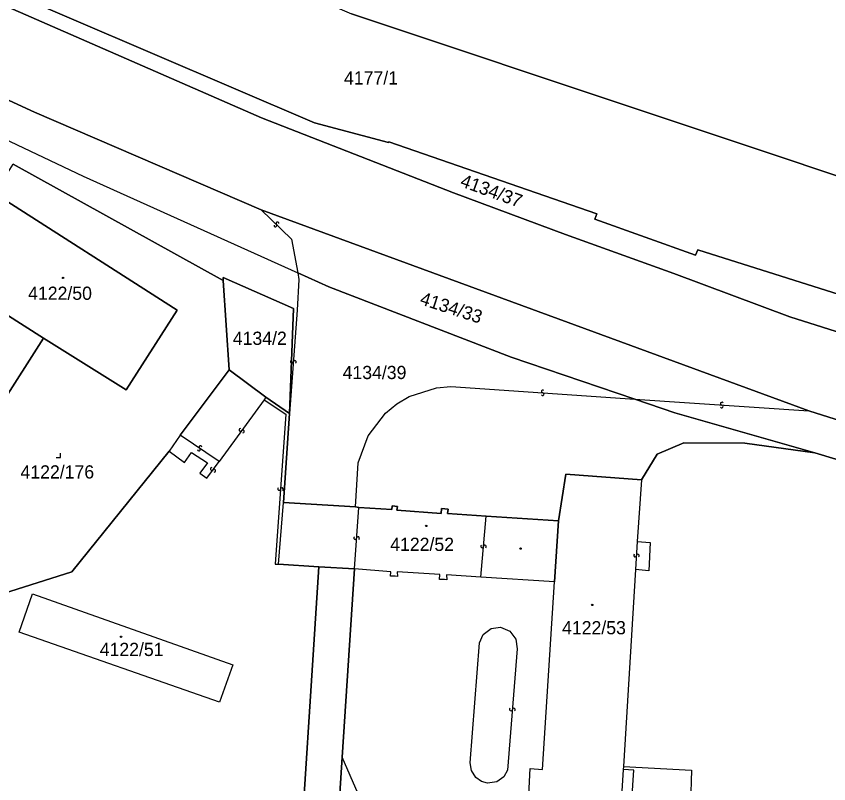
# Model space of a CAD drawing. Extents: x -598233 to -596890, y -1157848 to -1156431.
# Drawn here: x -597945.2 to -597840.5, y -1157611.2 to -1157512.4 of the extents above; entities that cross this region are included whole.
import ezdxf

# ---------------------------------------------------------------- set-up
doc = ezdxf.new("R2010")
doc.units = 0
for name, color, linetype in [('Level 1', 7, 'Continuous'), ('Level 13', 7, 'Continuous'), ('Level 3', 7, 'Continuous'), ('Level 4', 7, 'Continuous'), ('Level 5', 7, 'Continuous'), ('Level 57', 7, 'Continuous'), ('Level 60', 7, 'Continuous'), ('Vrstva 60', 7, 'Continuous')]:
    doc.layers.add(name, color=color, linetype=linetype)

msp = doc.modelspace()

# ---------------------------------------------------------------- linework, layer by layer
at = {"layer": 'Level 1'}
for points in [[(-597913.6, -1157537.3), (-597942.81, -1157524.72), (-597959.99, -1157516.81), (-597976.93, -1157508.35), (-597986.84, -1157503.35), (-597996.75, -1157497.54), (-598004.99, -1157491.79), (-598011.47, -1157486.71), (-598075.95, -1157430.81), (-598078.56, -1157429.36)], [(-598038.09, -1157453.32), (-598021.72, -1157467.23), (-598015.08, -1157472.26), (-598001.59, -1157481.46), (-597987.42, -1157490.71), (-597984.33, -1157492.5), (-597975.77, -1157497.25), (-597953.48, -1157507.99), (-597913.56, -1157525.44), (-597888.84, -1157535.12), (-597874.43, -1157540.49), (-597860.48, -1157545.51), (-597845.54, -1157551.08), (-597825.32, -1157557.5)], [(-597823.15, -1157553.3), (-597823.53, -1157553.16), (-597857.39, -1157542.48), (-597857.69, -1157543.15), (-597870.63, -1157538.52), (-597870.37, -1157537.84), (-597897.17, -1157528.53), (-597897.21, -1157528.65), (-597906.72, -1157526.08), (-597948.51, -1157508.17), (-597952.1, -1157506.41), (-597975.49, -1157494.97), (-597983.53, -1157490.82)], [(-597901.96, -1157512.06), (-597824.41, -1157537.97)], [(-597979.31, -1157512.67), (-597936.54, -1157532.96), (-597908.9, -1157545.41)], [(-597945.53, -1157531.41), (-597918.5, -1157546.39)], [(-597947.94, -1157535.19), (-597924.43, -1157550.22), (-597931, -1157560.5), (-597941.63, -1157553.83)], [(-597913.6, -1157537.3), (-597843.08, -1157563.22)], [(-597989.58, -1157543.55), (-597978.7, -1157561.72), (-597968.17, -1157576.4), (-597956.12, -1157589.86), (-597953.04, -1157588.7), (-597937.98, -1157583.96), (-597925.46, -1157568.41)], [(-597954.59, -1157545.6), (-597967.26, -1157565.3), (-597970.4, -1157563.29), (-597972.89, -1157567.17), (-597969.79, -1157569.25), (-597971.11, -1157571.47), (-597958.18, -1157579.74), (-597941.63, -1157553.83)], [(-597954.59, -1157545.6), (-597941.63, -1157553.83)], [(-597865.5, -1157561.69), (-597881.42, -1157556.29), (-597904.9, -1157547.21), (-597908.9, -1157545.41)], [(-597909.97, -1157563.55), (-597909.45, -1157550.01), (-597918.51, -1157546.01), (-597918.5, -1157546.39)], [(-597918.5, -1157546.39), (-597917.73, -1157557.9)], [(-597924.02, -1157566.34), (-597917.73, -1157557.9)], [(-597917.73, -1157557.9), (-597912.99, -1157561.42)], [(-597912.99, -1157561.42), (-597909.97, -1157563.55)], [(-597842.3, -1157568.62), (-597860.35, -1157563.44), (-597865.5, -1157561.69)], [(-597457.99, -1157648.3), (-597510.31, -1157637.9), (-597566.92, -1157626.51), (-597621.93, -1157615.29), (-597674.27, -1157604.65), (-597727.52, -1157593.95), (-597766.74, -1157585.27), (-597793.63, -1157578.19), (-597810.63, -1157573.46), (-597843.08, -1157563.22)], [(-597909.97, -1157563.55), (-597910.72, -1157575.03)], [(-597924.02, -1157566.34), (-597925.46, -1157568.41)], [(-597864.63, -1157572.11), (-597862.63, -1157568.77), (-597859.17, -1157567.31), (-597851.33, -1157567.38), (-597842.3, -1157568.62)], [(-597842.3, -1157568.62), (-597811.99, -1157577.74), (-597794.73, -1157582.38), (-597777.42, -1157587.05)], [(-597875.32, -1157577.36), (-597874.38, -1157571.36), (-597864.63, -1157572.11)], [(-597864.63, -1157572.11), (-597865.17, -1157580.04)], [(-597911.36, -1157582.95), (-597910.72, -1157575.03)], [(-597910.72, -1157575.03), (-597901.48, -1157575.59)], [(-597901.48, -1157575.59), (-597901.04, -1157575.64)], [(-597901.04, -1157575.64), (-597896.77, -1157575.93), (-597896.74, -1157575.45), (-597896.05, -1157575.53), (-597896.15, -1157576), (-597890.42, -1157576.43), (-597890.39, -1157575.78), (-597889.53, -1157575.88), (-597889.61, -1157576.42), (-597884.62, -1157576.75)], [(-597884.62, -1157576.75), (-597875.32, -1157577.36)], [(-597875.83, -1157585.25), (-597875.32, -1157577.36)], [(-597865.17, -1157580.04), (-597863.5, -1157580.15), (-597863.7, -1157583.8), (-597865.39, -1157583.63)], [(-597906.18, -1157583.28), (-597909.06, -1157627.95), (-598044.6, -1157619.18), (-598047.12, -1157656.06), (-598034.89, -1157656.85)], [(-597911.36, -1157582.95), (-597906.18, -1157583.28)], [(-597906.18, -1157583.28), (-597901.61, -1157583.57)], [(-597903.17, -1157607.81), (-597901.61, -1157583.57)], [(-597885.31, -1157584.61), (-597889.73, -1157584.35), (-597889.7, -1157584.98), (-597889.98, -1157584.95), (-597890.35, -1157584.93), (-597890.66, -1157584.95), (-597890.58, -1157584.3), (-597896.1, -1157583.95), (-597896.06, -1157584.55), (-597896.34, -1157584.52), (-597896.66, -1157584.51), (-597896.97, -1157584.52), (-597896.9, -1157583.93), (-597901.61, -1157583.57)], [(-597865.39, -1157583.63), (-597866.95, -1157609.01)], [(-597875.83, -1157585.25), (-597885.31, -1157584.61)], [(-597867, -1157609.41), (-597867.48, -1157617.05), (-597877.85, -1157616.75), (-597877.6, -1157612.76), (-597879.16, -1157612.66), (-597878.98, -1157609.3), (-597877.38, -1157609.4), (-597875.83, -1157585.25)], [(-597917.27, -1157595.91), (-597918.96, -1157600.75), (-597944.77, -1157591.72), (-597943.04, -1157586.79), (-597917.27, -1157595.91)], [(-597964.2, -1157694.04), (-597963.85, -1157688.75), (-597961.55, -1157671.94), (-597959.51, -1157642.87), (-597958.41, -1157630.64), (-597940.04, -1157631.73), (-597904.85, -1157633.91), (-597903.17, -1157607.81)], [(-597858.3, -1157613.77), (-597865.87, -1157613.39), (-597865.62, -1157609.5), (-597867, -1157609.41)], [(-597866.95, -1157609.01), (-597858.19, -1157609.5), (-597858.3, -1157613.77)]]:
    msp.add_lwpolyline(points, dxfattribs=at)
at = {"layer": 'Level 13'}
for centre, start, end in [((-597911.77, -1157539.31), 173.2026, 45.7926), ((-597911.51, -1157539.05), 353.4171, 225.5151), ((-597909.65, -1157556.87), 122.8681, 355.4581), ((-597909.29, -1157556.9), 303.0825, 175.1805), ((-597877.34, -1157560.7), 33.4865, 265.5845), ((-597877.36, -1157561.06), 213.272, 85.862), ((-597854.28, -1157562.28), 33.4688, 265.5668), ((-597854.3, -1157562.64), 213.2543, 85.8443), ((-597916.28, -1157565.64), 91.0453, 323.6353), ((-597915.98, -1157565.86), 271.2597, 143.3577), ((-597921.62, -1157568.18), 183.2608, 55.3588), ((-597921.42, -1157567.88), 3.0463, 235.6363), ((-597919.96, -1157570.69), 91.5351, 323.6331), ((-597919.66, -1157570.91), 271.3206, 143.9106), ((-597911.3, -1157573.28), 123.041, 355.631), ((-597910.94, -1157573.3), 303.2555, 175.3535), ((-597901.5, -1157579.59), 123.2614, 355.3594), ((-597901.14, -1157579.61), 303.047, 175.637), ((-597885.15, -1157580.66), 122.3558, 354.4538), ((-597884.79, -1157580.7), 302.1414, 174.7314), ((-597865.46, -1157581.83), 123.6515, 356.2415), ((-597865.1, -1157581.85), 303.866, 175.964), ((-597881.44, -1157601.67), 122.7372, 355.3272), ((-597881.08, -1157601.7), 302.9516, 175.0496)]:
    msp.add_arc(centre, 0.184, start, end, dxfattribs=at)
at = {"layer": 'Level 3'}
for points in [[(-597913.6, -1157537.3), (-597909.69, -1157541.07), (-597908.9, -1157545.41)], [(-597908.9, -1157545.41), (-597908.74, -1157546.3), (-597908.97, -1157550.22), (-597909.97, -1157563.55)], [(-597901.48, -1157575.59), (-597901.1, -1157569.9), (-597899.83, -1157566.43), (-597897.58, -1157563.5), (-597896.12, -1157562.3), (-597894.56, -1157561.37), (-597891.04, -1157560.24), (-597889.2, -1157560.08), (-597865.5, -1157561.69)], [(-597913.23, -1157561.77), (-597919.03, -1157569.72)], [(-597912.99, -1157561.42), (-597913.23, -1157561.77)], [(-597913.23, -1157561.77), (-597910.43, -1157563.63), (-597911.82, -1157582.94), (-597911.36, -1157582.95)], [(-597865.5, -1157561.69), (-597843.08, -1157563.22)], [(-597919.03, -1157569.72), (-597924.02, -1157566.34)], [(-597925.46, -1157568.41), (-597923.47, -1157569.84), (-597922.57, -1157568.56), (-597920.53, -1157569.9), (-597921.49, -1157571.25), (-597920.59, -1157571.88), (-597919.03, -1157569.72)], [(-597901.61, -1157583.57), (-597901.04, -1157575.64)], [(-597885.31, -1157584.61), (-597884.62, -1157576.75)], [(-597865.17, -1157580.04), (-597865.39, -1157583.63)], [(-597880.66, -1157593.86), (-597881.87, -1157609.51), (-597882.37, -1157610.34), (-597883.27, -1157610.98), (-597884.45, -1157611.15), (-597885.25, -1157610.94), (-597885.98, -1157610.42), (-597886.54, -1157609.52), (-597886.69, -1157608.55), (-597885.5, -1157593.11), (-597885.03, -1157592.03), (-597883.99, -1157591.24), (-597882.77, -1157591.08), (-597881.57, -1157591.58), (-597880.81, -1157592.62), (-597880.66, -1157593.86)], [(-597858.3, -1157613.77), (-597859.05, -1157616.73), (-597862.46, -1157618.98), (-597895.87, -1157615.74), (-597901.1, -1157612.53), (-597903.17, -1157607.81)], [(-597866.95, -1157609.01), (-597867, -1157609.41)]]:
    msp.add_lwpolyline(points, dxfattribs=at)
at = {"layer": 'Level 5'}
msp.add_lwpolyline([(-597939.99, -1157569.22), (-597939.44, -1157569.22), (-597939.44, -1157568.67)], dxfattribs=at)
for centre, radius in [((-597939.12, -1157546.07), 0.09), ((-597939.12, -1157546.07), 0.0521), ((-597892.35, -1157578.02), 0.09), ((-597892.35, -1157578.02), 0.0521), ((-597880.21, -1157580.95), 0.09), ((-597880.21, -1157580.95), 0.0521), ((-597870.98, -1157588.21), 0.09), ((-597870.98, -1157588.21), 0.0521), ((-597931.64, -1157592.31), 0.09), ((-597931.64, -1157592.31), 0.0521)]:
    msp.add_circle(centre, radius, dxfattribs=at)
at = {"layer": 'Level 60'}
for points in [[(-598204.12, -1157375.38), (-598162.81, -1157389.78), (-598072.83, -1157420.66), (-598059.61, -1157430.92), (-598057.43, -1157432.54), (-598036.51, -1157451.28), (-598021.29, -1157464.97), (-598000.88, -1157479.94), (-597986.22, -1157489.25), (-597983.53, -1157490.82), (-597975.49, -1157494.97), (-597952.1, -1157506.41), (-597948.51, -1157508.17), (-597906.72, -1157526.08), (-597897.21, -1157528.65), (-597897.17, -1157528.53), (-597870.37, -1157537.84), (-597870.63, -1157538.52), (-597857.69, -1157543.15), (-597857.39, -1157542.48), (-597823.53, -1157553.16)], [(-597825.32, -1157557.5), (-597845.54, -1157551.08), (-597860.48, -1157545.51), (-597874.43, -1157540.49), (-597888.84, -1157535.12), (-597913.56, -1157525.44), (-597953.48, -1157507.99), (-597975.77, -1157497.25), (-597984.33, -1157492.5), (-597987.42, -1157490.71), (-598001.59, -1157481.46), (-598015.08, -1157472.26), (-598021.72, -1157467.23), (-598038.09, -1157453.32), (-598059.04, -1157434.82), (-598061.54, -1157432.58), (-598064.3, -1157430.35), (-598067.2, -1157428.28), (-598070.18, -1157426.3), (-598072.97, -1157424.5), (-598076.22, -1157422.69), (-598080.43, -1157420.79), (-598164.16, -1157392.34)], [(-597823.53, -1157553.16), (-597857.39, -1157542.48), (-597857.69, -1157543.15), (-597870.63, -1157538.52), (-597870.37, -1157537.84), (-597897.17, -1157528.53), (-597897.21, -1157528.65), (-597906.72, -1157526.08), (-597948.51, -1157508.17), (-597952.1, -1157506.41), (-597975.49, -1157494.97), (-597983.53, -1157490.82), (-597983.33, -1157490.39), (-597979.84, -1157487.65), (-597980.01, -1157487.4), (-597971.65, -1157480.83), (-597951.77, -1157490.37), (-597951.9, -1157490.61), (-597945.93, -1157493.18), (-597928.39, -1157500.71), (-597926.24, -1157501.63), (-597901.96, -1157512.06), (-597824.41, -1157537.97)], [(-597824.41, -1157537.97), (-597901.96, -1157512.06)], [(-597979.31, -1157512.67), (-597936.54, -1157532.96), (-597908.9, -1157545.41), (-597904.9, -1157547.21), (-597881.42, -1157556.29), (-597865.5, -1157561.69), (-597860.35, -1157563.44), (-597842.3, -1157568.62), (-597851.33, -1157567.38), (-597859.17, -1157567.31), (-597862.63, -1157568.77), (-597864.63, -1157572.11), (-597874.38, -1157571.36), (-597875.32, -1157577.36), (-597884.62, -1157576.75), (-597889.61, -1157576.42), (-597889.53, -1157575.88), (-597890.39, -1157575.78), (-597890.42, -1157576.43), (-597896.15, -1157576), (-597896.05, -1157575.53), (-597896.74, -1157575.45), (-597896.77, -1157575.93), (-597901.04, -1157575.64), (-597901.48, -1157575.59), (-597910.72, -1157575.03), (-597909.97, -1157563.55), (-597909.45, -1157550.01), (-597918.51, -1157546.01), (-597918.5, -1157546.39), (-597945.53, -1157531.41)]]:
    msp.add_lwpolyline(points, dxfattribs=at)
for points in [[(-597918.5, -1157546.39), (-597917.73, -1157557.9), (-597924.02, -1157566.34), (-597925.46, -1157568.41), (-597937.98, -1157583.96), (-597953.04, -1157588.7), (-597956.12, -1157589.86), (-597968.17, -1157576.4), (-597978.7, -1157561.72), (-597989.58, -1157543.55), (-597988.8, -1157543.1), (-597955.28, -1157545.16), (-597954.59, -1157545.6), (-597967.26, -1157565.3), (-597970.4, -1157563.29), (-597972.89, -1157567.17), (-597969.79, -1157569.25), (-597971.11, -1157571.47), (-597958.18, -1157579.74), (-597941.63, -1157553.83), (-597931, -1157560.5), (-597924.43, -1157550.22), (-597947.94, -1157535.19), (-597945.53, -1157531.41)], [(-597941.63, -1157553.83), (-597954.59, -1157545.6), (-597947.94, -1157535.19), (-597924.43, -1157550.22), (-597931, -1157560.5)], [(-597954.59, -1157545.6), (-597941.63, -1157553.83), (-597958.18, -1157579.74), (-597971.11, -1157571.47), (-597969.79, -1157569.25), (-597972.89, -1157567.17), (-597970.4, -1157563.29), (-597967.26, -1157565.3)], [(-597912.99, -1157561.42), (-597917.73, -1157557.9), (-597918.5, -1157546.39), (-597918.51, -1157546.01), (-597909.45, -1157550.01), (-597909.97, -1157563.55)], [(-597875.32, -1157577.36), (-597874.38, -1157571.36), (-597864.63, -1157572.11), (-597865.17, -1157580.04), (-597863.5, -1157580.15), (-597863.7, -1157583.8), (-597865.39, -1157583.63), (-597866.95, -1157609.01), (-597858.19, -1157609.5), (-597858.3, -1157613.77), (-597865.87, -1157613.39), (-597865.62, -1157609.5), (-597867, -1157609.41), (-597867.48, -1157617.05), (-597877.85, -1157616.75), (-597877.6, -1157612.76), (-597879.16, -1157612.66), (-597878.98, -1157609.3), (-597877.38, -1157609.4), (-597875.83, -1157585.25)], [(-597901.04, -1157575.64), (-597896.77, -1157575.93), (-597896.74, -1157575.45), (-597896.05, -1157575.53), (-597896.15, -1157576), (-597890.42, -1157576.43), (-597890.39, -1157575.78), (-597889.53, -1157575.88), (-597889.61, -1157576.42), (-597884.62, -1157576.75), (-597875.32, -1157577.36), (-597875.83, -1157585.25), (-597885.31, -1157584.61), (-597889.73, -1157584.35), (-597889.7, -1157584.98), (-597889.98, -1157584.95), (-597890.35, -1157584.93), (-597890.66, -1157584.95), (-597890.58, -1157584.3), (-597896.1, -1157583.95), (-597896.06, -1157584.55), (-597896.34, -1157584.52), (-597896.66, -1157584.51), (-597896.97, -1157584.52), (-597896.9, -1157583.93), (-597901.61, -1157583.57), (-597906.18, -1157583.28), (-597911.36, -1157582.95), (-597910.72, -1157575.03), (-597901.48, -1157575.59)], [(-597909.06, -1157627.95), (-597906.18, -1157583.28), (-597901.61, -1157583.57), (-597903.17, -1157607.81), (-597904.85, -1157633.91), (-597940.04, -1157631.73), (-597958.41, -1157630.64), (-597959.51, -1157642.87), (-597961.55, -1157671.94), (-597963.85, -1157688.75), (-597964.2, -1157694.04), (-597966.74, -1157733.21), (-597966.34, -1157740.61), (-597969.13, -1157784.66), (-597977.32, -1157784.11), (-597967.14, -1157630.18), (-598032.81, -1157625.6), (-598034.89, -1157656.85), (-598047.12, -1157656.06), (-598044.6, -1157619.18)], [(-597917.27, -1157595.91), (-597918.96, -1157600.75), (-597944.77, -1157591.72), (-597943.04, -1157586.79)]]:
    msp.add_lwpolyline(points, close=True, dxfattribs=at)
at = {"layer": 'Vrstva 60'}
for points in [[(-598075.95, -1157430.81), (-598011.47, -1157486.71), (-598004.99, -1157491.79), (-597996.75, -1157497.54), (-597986.84, -1157503.35), (-597976.93, -1157508.35), (-597959.99, -1157516.81), (-597942.81, -1157524.72), (-597913.6, -1157537.3), (-597843.08, -1157563.22), (-597810.63, -1157573.46)], [(-597810.63, -1157573.46), (-597843.08, -1157563.22), (-597913.6, -1157537.3), (-597942.81, -1157524.72), (-597959.99, -1157516.81), (-597976.93, -1157508.35), (-597986.84, -1157503.35), (-597996.75, -1157497.54), (-598004.99, -1157491.79), (-598011.47, -1157486.71), (-598075.95, -1157430.81)], [(-597825.32, -1157557.5), (-597845.54, -1157551.08), (-597860.48, -1157545.51), (-597874.43, -1157540.49), (-597888.84, -1157535.12), (-597913.56, -1157525.44), (-597953.48, -1157507.99), (-597975.77, -1157497.25), (-597984.33, -1157492.5), (-597987.42, -1157490.71), (-598001.59, -1157481.46), (-598015.08, -1157472.26), (-598021.72, -1157467.23), (-598038.09, -1157453.32)], [(-598048.23, -1157458.48), (-598013.02, -1157489.13), (-598009.47, -1157492.21), (-597996.88, -1157500.62), (-597993.93, -1157502.7), (-597986.86, -1157507.68), (-597979.31, -1157512.67), (-597936.54, -1157532.96), (-597908.9, -1157545.41), (-597904.9, -1157547.21), (-597881.42, -1157556.29), (-597865.5, -1157561.69), (-597860.35, -1157563.44), (-597842.3, -1157568.62), (-597811.99, -1157577.74)], [(-597909.06, -1157627.95), (-597906.18, -1157583.28), (-597911.36, -1157582.95), (-597910.72, -1157575.03), (-597909.97, -1157563.55), (-597912.99, -1157561.42), (-597917.73, -1157557.9), (-597924.02, -1157566.34), (-597925.46, -1157568.41), (-597937.98, -1157583.96), (-597953.04, -1157588.7), (-597956.12, -1157589.86), (-597968.17, -1157576.4), (-597978.7, -1157561.72), (-597989.58, -1157543.55), (-597993.66, -1157546.2), (-597979.47, -1157570.71), (-597969.34, -1157585.52), (-597971.28, -1157611.07), (-597973.01, -1157610.9), (-597981.64, -1157610.29), (-597981.79, -1157612.44)], [(-597838.76, -1157614.97), (-597837.66, -1157598.53), (-597828.29, -1157599.15), (-597777.2, -1157602.47), (-597769.09, -1157603.03), (-597759.84, -1157603.69), (-597759.7, -1157601.52), (-597759.64, -1157600.91), (-597762.27, -1157600.72), (-597777.42, -1157587.05), (-597794.73, -1157582.38), (-597811.99, -1157577.74), (-597842.3, -1157568.62), (-597851.33, -1157567.38), (-597859.17, -1157567.31), (-597862.63, -1157568.77), (-597864.63, -1157572.11), (-597865.17, -1157580.04), (-597863.5, -1157580.15), (-597863.7, -1157583.8), (-597865.39, -1157583.63), (-597866.95, -1157609.01), (-597858.19, -1157609.5), (-597858.3, -1157613.77)], [(-597879.16, -1157612.66), (-597878.98, -1157609.3), (-597877.38, -1157609.4), (-597875.83, -1157585.25), (-597885.31, -1157584.61), (-597889.73, -1157584.35), (-597889.7, -1157584.98), (-597889.98, -1157584.95), (-597890.35, -1157584.93), (-597890.66, -1157584.95), (-597890.58, -1157584.3), (-597896.1, -1157583.95), (-597896.06, -1157584.55), (-597896.34, -1157584.52), (-597896.66, -1157584.51), (-597896.97, -1157584.52), (-597896.9, -1157583.93), (-597901.61, -1157583.57), (-597903.17, -1157607.81), (-597904.85, -1157633.91)], [(-597865.87, -1157613.39), (-597865.62, -1157609.5), (-597867, -1157609.41), (-597867.48, -1157617.05)]]:
    msp.add_lwpolyline(points, dxfattribs=at)
msp.add_lwpolyline([(-597944.77, -1157591.72), (-597943.04, -1157586.79), (-597917.27, -1157595.91), (-597918.96, -1157600.75)], close=True, dxfattribs=at)

# ---------------------------------------------------------------- texts
at = {"layer": 'Level 4'}
for s, p in [('4177/1', (-597902.94, -1157521.16)), ('4122/50', (-597943.62, -1157548.9)), ('4134/2', (-597917.26, -1157554.7)), ('4134/39', (-597903.12, -1157559.11)), ('4122/176', (-597944.6, -1157571.92)), ('4122/52', (-597896.99, -1157581.25)), ('4122/53', (-597874.86, -1157591.99)), ('4122/51', (-597934.4, -1157594.79))]:
    msp.add_text(s, height=1.7, dxfattribs=at).set_placement(p)
at = {"layer": 'Level 57'}
for s, rotation, p in [('4134/37', 340, (-597888.09, -1157534.24)), ('4134/33', 342, (-597893.29, -1157549.44))]:
    msp.add_text(s, height=1.7, rotation=rotation, dxfattribs=at).set_placement(p)

doc.saveas('drawing.dxf')
